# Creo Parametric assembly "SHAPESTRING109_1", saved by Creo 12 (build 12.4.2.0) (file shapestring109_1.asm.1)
Units: Custom; MM, KILOGRAM, SECS

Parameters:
  PTC_WM_ITERATION = "0"
  PTC_WM_VERSION = "-.0"
  PTC_WM_LIFECYCLE_STATE = "In Work"
  PTC_WM_LIFECYCLE = "MO_CADDocument"
  PTC_WM_CREATED_BY = "Maximilian Roepper (Z0017RMS: MO)"
  PTC_WM_CREATED_ON = "18-Sep-26 11:36:42 AM"
  PTC_WM_MODIFIED_BY = "Maximilian Roepper (Z0017RMS: MO)"
  PTC_WM_MODIFIED_ON = "18-Sep-26 11:36:46 AM"
  PDMLINKNUMBER = "PDM000071455189"
  PTC_WM_NUMBER = "PDM000071455189"

Other parameters: WEIGHT, WEIGHT_FACTOR, WEIGHT_ADD, MC_ERRORS, SUPPLIER

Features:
  1. coordinate system
  2. imported feature
  3. component "SHAPESTRING067_1"
  4. component "SHAPESTRING105_1"
  5. component "SHAPESTRING106_1"
  6. component "SHAPESTRING107_1"
  7. component "SHAPESTRING108_1"

Other named items: DRW_VIEW_ORG, ROUGH-GROB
